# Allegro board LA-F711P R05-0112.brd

Outline 371.4 x 140.3 mm; copper layers: TOP, GND1, IN1, VCC, IN2, IN3, GND2, BOTTOM. Coordinates in mm from the lower left corner of the outline.

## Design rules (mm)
net group 5: nets PCIE_PTX_C_DRX_N5 PCIE_PTX_C_DRX_P5
net group 6: nets PCIE_PTX_C_DRX_N6 PCIE_PTX_C_DRX_P6
net group 7: nets PCIE_PTX_C_DRX_N7 PCIE_PTX_C_DRX_P7
net group DDR_ALE_S12/25: nets DDR_A_ALERT# DDR_B_ALERT#
net group DIFFPAIR12: nets CPU_DP2_AUXN CPU_DP2_AUXP
net group DIFFPAIR14: nets CPU_DP2_N0 CPU_DP2_P0
net group DIFFPAIR15: nets CPU_DP2_N0_C CPU_DP2_P0_C
net group DIFFPAIR16: nets CPU_DP2_N1 CPU_DP2_P1
net group DIFFPAIR17: nets CPU_DP2_N1_C CPU_DP2_P1_C
net group DIFFPAIR18: nets CPU_DP2_N2 CPU_DP2_P2
net group DIFFPAIR19: nets CPU_DP2_N2_C CPU_DP2_P2_C
net group DIFFPAIR20: nets CPU_DP2_N3 CPU_DP2_P3
net group DIFFPAIR21: nets CPU_DP2_N3_C CPU_DP2_P3_C
net group DIFFPAIR22: nets CPU_DP3_AUXN CPU_DP3_AUXP
net group DIFFPAIR23: nets CPU_DP3_AUXN_C CPU_DP3_AUXP_C
net group DIFFPAIR24: nets CPU_DP3_N0 CPU_DP3_P0
net group DIFFPAIR25: nets CPU_DP3_N0_C CPU_DP3_P0_C
net group DIFFPAIR26: nets CPU_DP3_N1 CPU_DP3_P1
net group DIFFPAIR27: nets CPU_DP3_N1_C CPU_DP3_P1_C
net group DIFFPAIR28: nets CPU_DP3_N2 CPU_DP3_P2
net group DIFFPAIR30: nets CPU_DP3_N3 CPU_DP3_P3
net group DIFFPAIR344: nets CLK_TP_SIO_R DAT_TP_SIO_R
net group DIFFPAIR345: nets I2C1_SCK_TP_R I2C1_SDA_TP_R
net group DIFFPAIR346: nets I2C1_SCK_TP I2C1_SDA_TP
net group DIFFPAIR347: nets CLK_TP_SIO_I2C_DAT DAT_TP_SIO_I2C_CLK
net group DIFFPAIR349: nets DMI_CRX_PTX_N0 DMI_CRX_PTX_P0
net group DIFFPAIR350: nets DMI_CRX_PTX_N1 DMI_CRX_PTX_P1
net group DIFFPAIR351: nets DMI_CRX_PTX_N2 DMI_CRX_PTX_P2
net group DIFFPAIR352: nets DMI_CRX_PTX_N3 DMI_CRX_PTX_P3
net group DIFFPAIR353: nets DMI_CTX_PRX_N0 DMI_CTX_PRX_P0
net group DIFFPAIR354: nets DMI_CTX_PRX_N1 DMI_CTX_PRX_P1
net group DIFFPAIR355: nets DMI_CTX_PRX_N2 DMI_CTX_PRX_P2
net group DIFFPAIR356: nets DMI_CTX_PRX_N3 DMI_CTX_PRX_P3
net group DIFFPAIR357: nets HDMI_CTRL_CLK HDMI_CTRL_DATA
net group DIFFPAIR359: nets PCH_CL_CLK1 PCH_CL_DATA1
net group DIFFPAIR360: nets PCH_DP1_CTRL_CLK PCH_DP1_CTRL_DATA
net group DIFFPAIR361: nets PCH_DP3_CTRL_CLK PCH_DP3_CTRL_DATA
net group DIFFPAIR365: nets TBTA_DEBUG1 TBTA_DEBUG2
net group DIFFPAIR375: nets BC_CLK_ECE1117 BC_DAT_ECE1117
net group DIFFPAIR376: nets VCC_SA_SENSE VSS_SA_SENSE
net group DIFFPAIR377: nets VCC_SENSE VSS_SENSE
net group DIFFPAIR378: nets VCC_GT_SENSE VSS_GT_SENSE
net group DIFFPAIR380: nets VCC_IO_SENSE VSS_IO_SENSE
net group DIFFPAIR382: nets PCIE_PRX_C_DTX_N6 PCIE_PRX_C_DTX_P6
net group DIFFPAIR383: nets PCIE_PRX_DTX_N6 PCIE_PRX_DTX_P6
net group DIFFPAIR384: nets PCIE_PTX_DRX_N6 PCIE_PTX_DRX_P6
net group DIFFPAIR385: nets SD_1_N1 SD_1_P1
net group DIFFPAIR386: nets SD_1_DAT0 SD_1_DAT1
net group DIFFPAIR387: nets SD_1_DAT0_R SD_1_DAT1_R
net group DIFFPAIR388: nets SD_1_N0 SD_1_P0
net group DIFFPAIR389: nets SW_USB20_1_N4 SW_USB20_1_P4
net group DIFFPAIR390: nets SW_USB20_2_N4 SW_USB20_2_P4
net group DIFFPAIR391: nets SW_USB20_1_N4_R SW_USB20_1_P4_R
net group DIFFPAIR392: nets DP2_MIC_SBU1 DP2_MIC_SBU2
net group DIFFPAIR393: nets CNV_PRX_DTX_N1 CNV_PRX_DTX_P1
net group DIFFPAIR394: nets CNV_PRX_DTX_N0 CNV_PRX_DTX_P0
net group DIFFPAIR395: nets CLK_CNV_PRX_DTX_N CLK_CNV_PRX_DTX_P
net group DIFFPAIR396: nets CLK_CNV_PTX_DRX_N CLK_CNV_PTX_DRX_P
net group DIFFPAIR397: nets CNV_PTX_DRX_N1 CNV_PTX_DRX_P1
net group DIFFPAIR398: nets CNV_PTX_DRX_N0 CNV_PTX_DRX_P0
net group DIFFPAIR399: nets PCIE_PRX_C_DTX_N5 PCIE_PRX_C_DTX_P5
net group DIFFPAIR400: nets PCIE_PRX_DTX_N5 PCIE_PRX_DTX_P5
net group DIFFPAIR401: nets PCIE_PTX_DRX_N5 PCIE_PTX_DRX_P5
net group DIFFPAIR403: nets PCIE_PTX_L_DRX_N18 PCIE_PTX_L_DRX_P18
net group DIFFPAIR404: nets PCIE_PTX_SW_DRX_N18 PCIE_PTX_SW_DRX_P18
net group DIFFPAIR405: nets PCIE_PRX_SW_DTX_N18 PCIE_PRX_SW_DTX_P18
net group DIFFPAIR406: nets PCIE_PRX_DTX_N7 PCIE_PRX_DTX_P7
net group DIFFPAIR407: nets PCIE_PTX_DRX_N7 PCIE_PTX_DRX_P7
net group DIFFPAIR408: nets CPU_DP3_N1_RD CPU_DP3_P1_RD
net group DIFFPAIR409: nets CPU_DP3_N2_C_RD CPU_DP3_P2_C_RD
net group DIFFPAIR410: nets PS8802_SBU1_R PS8802_SBU2_R
net group DP1: nets CPU_DP3_AUXN_C_RD CPU_DP3_AUXP_C_RD
net group DP2: nets CPU_DP3_AUXN_RD CPU_DP3_AUXP_RD
net group DP3: nets CPU_DP3_N0_C_RD CPU_DP3_P0_C_RD
net group DP4: nets CPU_DP3_N0_RD CPU_DP3_P0_RD
net group DP5: nets CPU_DP3_N1_C_RD CPU_DP3_P1_C_RD
net group DP7: nets CPU_DP3_N3_C_RD CPU_DP3_P3_C_RD
net group DP18: nets USB20_N8_R USB20_P8_R
net group DP19: nets USB20_N14 USB20_P14
net group DP20: nets USB20_N14_R USB20_P14_R
net group DP21: nets CHR_USB20_N1 CHR_USB20_P1
net group DP22: nets CHR_USB20_N1_R CHR_USB20_P1_R
net group PCIE_PRX_DTX_P18: nets PCIE_PRX_DTX_N18 PCIE_PRX_DTX_P18
net group PCIE_PTX_DRX_P18: nets PCIE_PTX_DRX_N18 PCIE_PTX_DRX_P18
net group SW_USB20_2_N4_R: nets SW_USB20_2_N4_R SW_USB20_2_P4_R
net group TBT_S20/20: nets TBTA_DEBUG3 TBTA_DEBUG4
net group USB3.1: nets TBTA_LSRX_R TBTA_LSTX_R
net group USB3_DP2_1_MRX_C_DTX_P5: nets USB3_DP2_1_MRX_C_DTX_N5 USB3_DP2_1_MRX_C_DTX_P5
net group USB3_DP2_2_MRX_C_DTX_N5: nets USB3_DP2_2_MRX_C_DTX_N5 USB3_DP2_2_MRX_C_DTX_P5
net group W5: nets EDP_COMP PEG_COMP
net group W15: nets PCIECOMP PCIECOMP#
net group 50H-CLK-1234: nets AUD_AZACPU_SCLK AUD_AZACPU_SCLK_R CPU_XDP_TCLK DMIC_CLK0 DMIC_CLK_CODEC ESPI_CLK HDA_BIT_CLK HDA_BIT_CLK_R SUSCLK
net group 50H_CLK: nets PCH_SPI_CLK PCH_SPI_CLK_0_R PCH_SPI_CLK_1_R PCH_SPI_CLK_2_R PCH_SPI_CLK_R1
net group 50H_SPI: nets CPU_XDP_PRS PCH_SPI_CS#0 PCH_SPI_CS#0_R1 PCH_SPI_CS#0_R2 PCH_SPI_CS#1 PCH_SPI_CS#1_R1 PCH_SPI_CS#2 PCH_SPI_CS#2_R PCH_SPI_D0 PCH_SPI_D0_0_R PCH_SPI_D0_1_R PCH_SPI_D0_2_R PCH_SPI_D0_R1 PCH_SPI_D1 PCH_SPI_D1_0_R PCH_SPI_D1_1_R PCH_SPI_D1_2_R PCH_SPI_D1_R1 PCH_SPI_D2 PCH_SPI_D2_0_R PCH_SPI_D2_1_R PCH_SPI_D2_R1 PCH_SPI_D2_XDP PCH_SPI_D3 PCH_SPI_D3_0_R PCH_SPI_D3_1_R PCH_SPI_D3_R1
net group 100H_LANTF_4.5/5.5/5.5/5.5/4.5: nets RJ45_MDIN0 RJ45_MDIN1 RJ45_MDIN2 RJ45_MDIN3 RJ45_MDIP0 RJ45_MDIP1 RJ45_MDIP2 RJ45_MDIP3
net group CARD READER: nets SD_1_CLK SD_1_CLK_R SD_1_CMD SD_1_CMD_R SD_1_DAT2 SD_1_DAT2_R SD_1_DAT3 SD_1_DAT3_R
net group CLK: nets CLKREQ_PCIE#0 CLKREQ_PCIE#1 CLKREQ_PCIE#3 CLKREQ_PCIE#4 CLKREQ_PCIE#5 CLKREQ_PCIE#6_R CLKREQ_PCIE#7_R ESPI_CLK_5105 PCI_CLK_LPC1 XCLK_RBIAS XTAL24_IN_R XTAL24_OUT_R XTAL24_OUT_R1
net group CLK_S15/20: nets CLKREQ_PCIE#0_R CLKREQ_PCIE#1_R CLKREQ_PCIE#3_R CLKREQ_PCIE#4_R CLKREQ_PCIE#5_R PCH_JTAGX SUSCLK_R TBTA_ROM_CLK_PD TBTA_ROM_CLK_PD_R WIGIG_32KHZ
net group DDR_A_S12/25: nets DDR_A_ACT# DDR_A_BA0 DDR_A_BA1 DDR_A_BG0 DDR_A_BG1 DDR_A_MA0 DDR_A_MA1 DDR_A_MA2 DDR_A_MA3 DDR_A_MA4 DDR_A_MA5 DDR_A_MA6 DDR_A_MA7 DDR_A_MA8 DDR_A_MA9 DDR_A_MA10 DDR_A_MA11 DDR_A_MA12 DDR_A_MA13 DDR_A_MA14 DDR_A_MA15 DDR_A_MA16 DDR_A_PAR DDR_B_ACT# DDR_B_BA0 DDR_B_BA1 DDR_B_BG0 DDR_B_BG1 DDR_B_MA0 DDR_B_MA1 DDR_B_MA2 DDR_B_MA3 DDR_B_MA4 DDR_B_MA5 DDR_B_MA6 DDR_B_MA7 DDR_B_MA8 DDR_B_MA9 DDR_B_MA10 DDR_B_MA11 DDR_B_MA12 DDR_B_MA13 DDR_B_MA14 DDR_B_MA15 DDR_B_MA16 DDR_B_PAR
net group DDR_C_S12/25: nets DDR_A_CS#0 DDR_A_CS#1 DDR_A_ODT0 DDR_A_ODT1 DDR_B_CS#0 DDR_B_CS#1 DDR_B_ODT0 DDR_B_ODT1
net group DDR_CKE_S12/25: nets DDR_A_CKE0 DDR_A_CKE1 DDR_B_CKE0 DDR_B_CKE1
net group DDR_DQS_S5(16)/25: nets DDR_A_DQS0 DDR_A_DQS1 DDR_A_DQS2 DDR_A_DQS3 DDR_A_DQS4 DDR_A_DQS5 DDR_A_DQS6 DDR_A_DQS7 DDR_A_DQS#0 DDR_A_DQS#1 DDR_A_DQS#2 DDR_A_DQS#3 DDR_A_DQS#4 DDR_A_DQS#5 DDR_A_DQS#6 DDR_A_DQS#7 DDR_B_DQS0 DDR_B_DQS1 DDR_B_DQS2 DDR_B_DQS3 DDR_B_DQS4 DDR_B_DQS5 DDR_B_DQS6 DDR_B_DQS7 DDR_B_DQS#0 DDR_B_DQS#1 DDR_B_DQS#2 DDR_B_DQS#3 DDR_B_DQS#4 DDR_B_DQS#5 DDR_B_DQS#6 DDR_B_DQS#7
net group DDR_RCOMP_S20/25: nets DDR_RCOMP0 DDR_RCOMP1 DDR_RCOMP2
net group DDR_RESET_S4: nets DDR4_DRAMRST#_PCH
net group DDRA_D0_S8/5(16)/25: nets DDR_A_D0 DDR_A_D1 DDR_A_D2 DDR_A_D3 DDR_A_D4 DDR_A_D5 DDR_A_D6 DDR_A_D7
net group DDRA_D1_S8/5(16)/25: nets DDR_A_D8 DDR_A_D9 DDR_A_D10 DDR_A_D11 DDR_A_D12 DDR_A_D13 DDR_A_D14 DDR_A_D15
net group DDRA_D2_S8/5(16)/25: nets DDR_A_D16 DDR_A_D17 DDR_A_D18 DDR_A_D19 DDR_A_D20 DDR_A_D21 DDR_A_D22 DDR_A_D23
net group DDRA_D3_S8/5(16)/25: nets DDR_A_D24 DDR_A_D25 DDR_A_D26 DDR_A_D27 DDR_A_D28 DDR_A_D29 DDR_A_D30 DDR_A_D31
net group DDRA_D4_S8/5(16)/25: nets DDR_A_D32 DDR_A_D33 DDR_A_D34 DDR_A_D35 DDR_A_D36 DDR_A_D37 DDR_A_D38 DDR_A_D39
net group DDRA_D5_S8/5(16)/25: nets DDR_A_D40 DDR_A_D41 DDR_A_D42 DDR_A_D43 DDR_A_D44 DDR_A_D45 DDR_A_D46 DDR_A_D47
net group DDRA_D6_S8/5(16)/25: nets DDR_A_D48 DDR_A_D49 DDR_A_D50 DDR_A_D51 DDR_A_D52 DDR_A_D53 DDR_A_D54 DDR_A_D55
net group DDRA_D7_S8/5(16)/25: nets DDR_A_D56 DDR_A_D57 DDR_A_D58 DDR_A_D59 DDR_A_D60 DDR_A_D61 DDR_A_D62 DDR_A_D63
net group DDRB_D0_S8/5(16)/25: nets DDR_B_D0 DDR_B_D1 DDR_B_D2 DDR_B_D3 DDR_B_D4 DDR_B_D5 DDR_B_D6 DDR_B_D7
net group DDRB_D1_S8/5(16)/25: nets DDR_B_D8 DDR_B_D9 DDR_B_D10 DDR_B_D11 DDR_B_D12 DDR_B_D13 DDR_B_D14 DDR_B_D15
net group DDRB_D2_S8/5(16)/25: nets DDR_B_D16 DDR_B_D17 DDR_B_D18 DDR_B_D19 DDR_B_D20 DDR_B_D21 DDR_B_D22 DDR_B_D23
net group DDRB_D3_S8/5(16)/25: nets DDR_B_D24 DDR_B_D25 DDR_B_D26 DDR_B_D27 DDR_B_D28 DDR_B_D29 DDR_B_D30 DDR_B_D31
net group DDRB_D4_S8/5(16)/25: nets DDR_B_D32 DDR_B_D33 DDR_B_D34 DDR_B_D35 DDR_B_D36 DDR_B_D37 DDR_B_D38 DDR_B_D39
net group DDRB_D5_S8/5(16)/25: nets DDR_B_D40 DDR_B_D41 DDR_B_D42 DDR_B_D43 DDR_B_D44 DDR_B_D45 DDR_B_D46 DDR_B_D47
net group DDRB_D6_S8/5(16)/25: nets DDR_B_D48 DDR_B_D49 DDR_B_D50 DDR_B_D51 DDR_B_D52 DDR_B_D53 DDR_B_D54 DDR_B_D55
net group DDRB_D7_S8/5(16)/25: nets DDR_B_D56 DDR_B_D57 DDR_B_D58 DDR_B_D59 DDR_B_D60 DDR_B_D61 DDR_B_D62 DDR_B_D63
net group DDRCLK_S16/25: nets DDR_A_CLK0 DDR_A_CLK1 DDR_A_CLK#0 DDR_A_CLK#1 DDR_B_CLK0 DDR_B_CLK1 DDR_B_CLK#0 DDR_B_CLK#1
net group DIFFPAIR13: nets CPU_DP2_AUXN_C
net group DIFFPAIR326: nets PBAT_CHARGER_SMBDAT
net group DIFFPAIR327: nets PBAT_SMBDAT_C
net group DIFFPAIR329: nets DDR_XDP_WAN_SMBDAT
net group DIFFPAIR332: nets MEM_SMBDATA
net group DIFFPAIR333: nets SML0_SMBDATA
net group DIFFPAIR334: nets SML1_SMBDATA
net group DIFFPAIR335: nets UPD1_SMBDAT
net group DIFFPAIR336: nets UPD1_SMBDAT_Q
net group DIFFPAIR337: nets UPD2_SMBDAT
net group DP: nets CPU_DP1_N0 CPU_DP1_N1 CPU_DP1_N2 CPU_DP1_N3 CPU_DP1_P0 CPU_DP1_P1 CPU_DP1_P2 CPU_DP1_P3 CPU_DP2_AUXN_C_MUX CPU_DP2_AUXP_C CPU_DP2_AUXP_C_MUX
net group EDP_S12/15: nets EDP_AUXN EDP_AUXN_C EDP_AUXP EDP_AUXP_C EDP_TXN0 EDP_TXN0_C EDP_TXN1 EDP_TXN1_C EDP_TXP0 EDP_TXP0_C EDP_TXP1 EDP_TXP1_C
net group HDMI_S12/15: nets HDMI_CLKN HDMI_CLKP HDMI_L_CLKN HDMI_L_CLKP HDMI_L_TX_N0 HDMI_L_TX_N1 HDMI_L_TX_N2 HDMI_L_TX_P0 HDMI_L_TX_P1 HDMI_L_TX_P2 HDMI_TX_N0 HDMI_TX_N1 HDMI_TX_N2 HDMI_TX_P0 HDMI_TX_P1 HDMI_TX_P2
net group LAN_S20/20: nets LAN_MDIN0 LAN_MDIN0_L LAN_MDIN1 LAN_MDIN1_L LAN_MDIN2 LAN_MDIN2_L LAN_MDIN3 LAN_MDIN3_L LAN_MDIP0 LAN_MDIP0_L LAN_MDIP1 LAN_MDIP1_L LAN_MDIP2 LAN_MDIP2_L LAN_MDIP3 LAN_MDIP3_L
net group PCIE: nets PCIE_PRX_L_DTX_N18 PCIE_PRX_L_DTX_P18 PCIE_PTX_C_DRX_N18 PCIE_PTX_C_DRX_P18 PCIE_PTX_C_SW_DRX_N18 PCIE_PTX_C_SW_DRX_P18
net group PCIE_S12/12: nets PCIE_PRX_DTX_N9 PCIE_PRX_DTX_N10 PCIE_PRX_DTX_N11 PCIE_PRX_DTX_N12 PCIE_PRX_DTX_N17 PCIE_PRX_DTX_P9 PCIE_PRX_DTX_P10 PCIE_PRX_DTX_P11 PCIE_PRX_DTX_P12 PCIE_PRX_DTX_P17 PCIE_PTX_C_DRX_N9 PCIE_PTX_C_DRX_N10 PCIE_PTX_C_DRX_N11 PCIE_PTX_C_DRX_N12 PCIE_PTX_C_DRX_N17 PCIE_PTX_C_DRX_P9 PCIE_PTX_C_DRX_P10 PCIE_PTX_C_DRX_P11 PCIE_PTX_C_DRX_P12 PCIE_PTX_C_DRX_P17 PCIE_PTX_DRX_N9 PCIE_PTX_DRX_N10 PCIE_PTX_DRX_N11 PCIE_PTX_DRX_N12 PCIE_PTX_DRX_N17 PCIE_PTX_DRX_P9 PCIE_PTX_DRX_P10 PCIE_PTX_DRX_P11 PCIE_PTX_DRX_P12 PCIE_PTX_DRX_P17
net group PLATFORM CLK: nets CLK_PCIE_N0 CLK_PCIE_N1 CLK_PCIE_N3 CLK_PCIE_N4 CLK_PCIE_N5 CLK_PCIE_P0 CLK_PCIE_P1 CLK_PCIE_P3 CLK_PCIE_P4 CLK_PCIE_P5 CPU_24MHZ_R_D CPU_24MHZ_R_D# PCH_CPU_BCLK_D PCH_CPU_BCLK_D# PCH_CPU_BCLK_R_D PCH_CPU_BCLK_R_D# PCH_CPU_NSSC_CLK_D PCH_CPU_NSSC_CLK_D# PCH_CPU_PCIBCLK_D PCH_CPU_PCIBCLK_D# PCH_CPU_PCIBCLK_R_D PCH_CPU_PCIBCLK_R_D# PCH_XDP_CLK_DN PCH_XDP_CLK_DN_R PCH_XDP_CLK_DP PCH_XDP_CLK_DP_R
net group RTC: nets PCH_RTCX1 PCH_RTCX1_R PCH_RTCX2 SRTCRST#
net group S5/15: nets AUD_AZACPU_SDI AUD_AZACPU_SDI_R AUD_AZACPU_SDO AUD_AZACPU_SDO_R DMIC0 HDA_RST# HDA_RST#_R HDA_SDIN0 HDA_SDIN0_R HDA_SDOUT HDA_SDOUT_R HDA_SYNC HDA_SYNC_R
net group S8: nets ESPI_ALERT# ESPI_CS# ESPI_IO0 ESPI_IO0_R ESPI_IO1 ESPI_IO1_R ESPI_IO2 ESPI_IO2_R ESPI_IO3 ESPI_IO3_R ESPI_RESET#
net group S10: nets +LINE1-VREFO-L +LINE1-VREFO-R +MIC2-VREFO AUD_HP_NB_SENSE AUD_HP_OUT_L AUD_HP_OUT_L1 AUD_HP_OUT_R AUD_HP_OUT_R1 AUD_SENSE_A HP_OUT_L HP_OUT_R LINE1_L LINE1_R RING2 RING2_R SLEEVE SLEEVE_R
net group S12: nets CPU_2_PCH_TRIGGER CPU_2_PCH_TRIGGER_R H_CATERR# H_PROCHOT#_R H_PWRGD H_THERMTRIP# H_THERMTRIP#_R PCH_2_CPU_TRIGGER PCH_2_CPU_TRIGGER_R PCH_PLTRST# PCH_PLTRST#_5105 PCH_PLTRST#_AND PCH_PLTRST#_EC PCH_THERMTRIP# PLTRST_CPU# PLTRST_LAN# PLTRST_TPM# VCCST_PWRGD VCCST_PWRGD_CPU VCCST_PWRGD_EC XDP_OBS0 XDP_OBS0_R XDP_OBS1 XDP_OBS1_R
net group S15: nets DDR_XDP_WAN_SMBCLK H_VCCST_PWRGD_XDP ISH_UART0_CTS# ISH_UART0_CTS#_R ISH_UART0_RTS# ISH_UART0_RTS#_R ISH_UART0_RXD ISH_UART0_RXD_R ISH_UART0_TXD ISH_UART0_TXD_R MEM_SMBCLK PBAT_CHARGER_SMBCLK PBAT_SMBCLK_C PCH_CL_RST1# PCH_DPWROK PCH_DPWROK_EC PCH_INTRUDER_HDR# PCH_PCIE_WAKE# PCH_PWROK PCH_RSMRST#_AND PCH_RTCRST# PCIE_WAKE# PCIE_WAKE#_R SIO_PWRBTN# SIO_RCIN# SML0_SMBCLK SML1_SMBCLK SYS_PWROK SYS_PWROK_R SYS_RESET# UPD1_SMBCLK UPD1_SMBCLK_Q UPD2_SMBCLK USB2_COMP XDP_DBRESET#
net group S18: nets H_PECI PCH_PECI PECI_EC_R
net group S20: nets MEC_XTAL1 MEC_XTAL2 MEC_XTAL2_R XTAL24_IN_R1 XTAL24_OUT XTALI XTALO XTALO_R
net group S40: nets H_PM_DOWN H_PM_DOWN_R H_PM_SYNC H_PM_SYNC_R
net group SATA_S15(12)/15(12): nets SATA_PRX_C_DTX_N2 SATA_PRX_C_DTX_P2 SATA_PRX_C_RD_DTX_N2 SATA_PRX_C_RD_DTX_P2 SATA_PRX_DTX_N2 SATA_PRX_DTX_P2 SATA_PRX_RD_DTX_N2 SATA_PRX_RD_DTX_P2 SATA_PTX_C_DRX_N2 SATA_PTX_C_DRX_P2 SATA_PTX_C_RD_DRX_N2 SATA_PTX_C_RD_DRX_P2 SATA_PTX_DRX_N2 SATA_PTX_DRX_P2 SATA_PTX_RD_DRX_N2 SATA_PTX_RD_DRX_P2
net group SD: nets SD_1_CD# SDWP SDWP_Q
net group SIM: nets UIM_CLK UIM_DATA UIM_RESET
net group SPI: nets PCH_SPI_CS#0_R3
net group SVID: nets CPU_VIDALERT# VR_SVID_ALERT# VR_SVID_CLK VR_SVID_DATA
net group USB2_S12/12: nets USB20_N1 USB20_N2 USB20_N2_R USB20_N3 USB20_N3_R USB20_N4 USB20_N6 USB20_N8 USB20_N9 USB20_N9_R USB20_N10 USB20_N11 USB20_N11_R USB20_P1 USB20_P2 USB20_P2_R USB20_P3 USB20_P3_R USB20_P4 USB20_P6 USB20_P8 USB20_P9 USB20_P9_R USB20_P10 USB20_P11 USB20_P11_R
net group USB3-80H: nets USB3_PRX_C_MTX_N5 USB3_PRX_C_MTX_P5 USB3_PRX_MTX_N5 USB3_PRX_MTX_P5 USB3_PTX_C_MRX_N5 USB3_PTX_C_MRX_P5 USB3_PTX_MRX_N5 USB3_PTX_MRX_P5
net group USB3.1-100H: nets USB3_DP2_1_MRX_DTX_N5 USB3_DP2_1_MRX_DTX_P5 USB3_DP2_1_MTX_C_DRX_N5 USB3_DP2_1_MTX_C_DRX_P5 USB3_DP2_1_MTX_DRX_N5 USB3_DP2_1_MTX_DRX_P5 USB3_DP2_2_MRX_DTX_N5 USB3_DP2_2_MRX_DTX_P5 USB3_DP2_2_MTX_C_DRX_N5 USB3_DP2_2_MTX_C_DRX_P5 USB3_DP2_2_MTX_DRX_N5 USB3_DP2_2_MTX_DRX_P5
net group USB3_S12/12: nets USB3_PRX_DTX_N1 USB3_PRX_DTX_N2 USB3_PRX_DTX_N3 USB3_PRX_DTX_N4 USB3_PRX_DTX_P1 USB3_PRX_DTX_P2 USB3_PRX_DTX_P3 USB3_PRX_DTX_P4 USB3_PTX_C_DRX_N1 USB3_PTX_C_DRX_N2 USB3_PTX_C_DRX_N3 USB3_PTX_C_DRX_N4 USB3_PTX_C_DRX_P1 USB3_PTX_C_DRX_P2 USB3_PTX_C_DRX_P3 USB3_PTX_C_DRX_P4 USB3_PTX_DRX_N1 USB3_PTX_DRX_N2 USB3_PTX_DRX_N3 USB3_PTX_DRX_N4 USB3_PTX_DRX_P1 USB3_PTX_DRX_P2 USB3_PTX_DRX_P3 USB3_PTX_DRX_P4
net group VGA_C_S5/10: nets CLK_DDC2_CRT DAT_DDC2_CRT ISPSCL ISPSDA
net group VGA_S20/30: nets BLUE BLUE_CRT GREEN GREEN_CRT RED RED_CRT
net group VGA_SYNC_S12/20: nets HSYNC_CONN HSYNC_CRT VSYNC_CONN VSYNC_CRT
net group W5S5: nets REM_DIODE1_N REM_DIODE1_P REM_DIODE2_N REM_DIODE2_P REM_DIODE4_N REM_DIODE4_P
net group W10: nets BAT1_LED# BAT2_LED# BATT_WHITE# BATT_YELLOW#
net group W20: nets +DDR_VREF_A_CA +DDR_VREF_B_CA +DDR_VREF_B_DQ +DDR_VREF_CA
net group W20-POWER: nets +1.0V_AMPHYPLL +1.0V_PRIM_XDP +1.0V_VCCSTG +1.2V_LDO +1.8V_RUN_CARD +1.8VALWP +1VS_VCCIOP +3.3V_ALW2 +3.3V_ALWP +3.3V_CAM +3.3V_HDD +3.3V_LAN +3.3V_LAN_UZ2 +3.3V_MMI_AUX +3.3V_MMI_IN +3.3V_RTC_LDO +3.3V_RUN_CARD +3.3V_RUN_UZ3 +3.3V_TP +5V_ALW2 +5V_ALWP +5V_RUN_AUDIO +5V_TSP +5V_USB_CHG_PWR +BL_PWR_SRC +COINCELL +DC_IN_SS +DCIN_JACK +EDP_VDD +GND_CHASSIS +LCDVDD +PBATT +PECI_VREF +PWR_SRC_AC +RSVD_VCC3P3_1 +RTC_CELL +RTC_CELL_VBAT +SDC_IN +VCHGR +VDDA_AVDD1 +VR_CAP
net group W40: nets INT_SPK_L+ INT_SPK_L- INT_SPK_R+ INT_SPK_R- INT_SPKR_L+ INT_SPKR_L- INT_SPKR_R+ INT_SPKR_R-
nets with their own width: min track width 0.152; nets VCCMPHY_SENSE VSSMPHY_SENSE
nets with their own width: min track width 0.508; nets +3.3V_M_TPM +UZ12_TPM

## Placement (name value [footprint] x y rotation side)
CA1  680P_0402_50V7K  [C_0402]  349.17 37.92 90 bottom
CA2  330P_0402_50V8J  [C_0402]  354.38 31.19 90 top
CA3  330P_0402_50V8J  [C_0402]  350.19 31.44 90 top
CA4  680P_0402_50V7K  [C_0402]  349.07 34.9 90 bottom
CA5  27P_0402_50V8J  [C_0402]  121.7 103.42 270 bottom
CA6  82P_0402_50V8J  [C_0402]  122.97 103.42 270 bottom
CA7  0.1U_0201_10V6K  [C_0201]  120.72 103.72 180 bottom
CA8  0.1U_0201_10V6K  [C_0201]  344.56 42.57 0 top
CA9  10U_0603_10V6M  [C_0603]  345.07 43.49 90 top
CA10  0.1U_0201_10V6K  [C_0201]  338.79 33.3 180 top
CA12  680P_0402_50V7K  [C_0402]  349.86 39.71 45 bottom
CA13  680P_0402_50V7K  [C_0402]  352.8 38.07 225 bottom
CA19  1000P_0402_50V7K  [C_0402]  334.92 35.1 180 top
CA22  1000P_0402_50V7K  [C_0402]  334.92 37.77 180 top
CA23  1000P_0402_50V7K  [C_0402]  334.92 36.88 180 top
CA24  1000P_0402_50V7K  [C_0402]  334.92 35.99 180 top
CA25  10U_0603_10V6M  [C_0603]  346.72 38.15 0 top
CA27  0.1U_0402_25V6  [C_0402]  350.54 34.53 180 top
CA28  0.1U_0402_25V6  [C_0402]  347.94 35.49 180 top
CA29  1U_0603_10V6K  [C_0603]  339.71 40.82 180 bottom
CA31  1U_0603_10V6K  [C_0603]  336.19 32.47 270 top
CA33  10P_0402_50V8J  [C_0402]  341.55 29.06 270 top
CA35  2.2U_0402_6.3V6M  [C_0402]  343.99 43.79 90 top
CA41  0.1U_0402_25V6  [C_0402]  347.19 33.17 0 top
CA43  10U_0603_10V6M  [C_0603]  346.85 42.53 0 top
CA44  10U_0603_10V6M  [C_0603]  346.85 41.26 0 top
CA45  0.1U_0201_10V6K  [C_0201]  333.74 39.42 90 top
CA46  10U_0603_10V6M  [C_0603]  332.94 39.23 180 top
CA47  0.1U_0201_10V6K  [C_0201]  335.96 33.84 270 top
CA48  10U_0603_10V6M  [C_0603]  334.82 33.87 270 top
CA49  1U_0603_10V6K  [C_0603]  339.42 42.6 180 top
CA51  10U_0603_10V6M  [C_0603]  343.93 43.42 90 bottom
CA52  10U_0603_10V6M  [C_0603]  336.72 40.66 90 top
CA53  10U_0603_10V6M  [C_0603]  341.51 34.72 0 bottom
CA54  100P_0402_50V8J~D  [C_0402]  340.66 29.06 270 top
CA55  0.1U_0201_10V6K  [C_0201]  343.25 33.39 0 bottom
CA56  10U_0603_10V6M  [C_0603]  343.55 32.56 270 bottom
CA57  0.1U_0201_10V6K  [C_0201]  336.28 39.04 180 top
CA58  10U_0603_10V6M  [C_0603]  336.23 43.49 90 top
CA59  10U_0603_10V6M  [C_0603]  333.61 27.71 0 top
CA60  0.1U_0201_10V6K  [C_0201]  331.77 32.17 90 top
CA61  10U_0603_10V6M  [C_0603]  338.69 32.41 180 top
CA62  100P_0402_50V8J  [C_0402]  352.66 36.91 45 top
CA63  12P_0402_50V8J  [C_0402]  334.06 29.26 0 top
CA64  68P_0402_50V8J  [C_0402]  334.06 30.15 0 top
CA65  12P_0402_50V8J  [C_0402]  334.03 44.89 180 top
CA66  68P_0402_50V8J  [C_0402]  335.58 47.65 90 top
CA67  12P_0402_50V8J  [C_0402]  338.55 27.2 0 top
CA68  68P_0402_50V8J  [C_0402]  345.23 30.71 270 top
CA69  33P_0402_50V8J  [C_0402]  338.62 45.33 90 top
CA72  100P_0402_50V8J  [C_0402]  353.29 36.28 45 top
CA73  2P_0402_50V8C  [C_0402]  217.71 39.8 270 bottom
CA74  2P_0402_50V8C  [C_0402]  220.07 37.5 180 bottom
CA75  2P_0402_50V8C  [C_0402]  219.17 40.94 270 bottom
CA76  2P_0402_50V8C  [C_0402]  219.5 38.58 180 bottom
CC28  0.1U_0402_25V6  [C_0402]  41.91 36.47 180 top
CC29  0.1U_0402_25V6  [C_0402]  41.05 48.1 90 top
CC32  0.1U_0402_25V6  [C_0402]  44.73 48.15 90 top
CC33  0.1U_0402_25V6  [C_0402]  53.26 44.78 90 top
CC81  22U_0603_6.3V6M  [C_0603]  114.33 44.88 45 top
CC82  22U_0603_6.3V6M  [C_0603]  103.84 48.29 0 top
CC83  22U_0603_6.3V6M  [C_0603]  96.48 48.07 0 top
CC84  22U_0603_6.3V6M  [C_0603]  112.56 46.66 45 top
CC161  10U_0603_6.3V6M~D  [C_0603]  93.4 59.56 180 top
CC163  10U_0603_6.3V6M~D  [C_0603]  96.99 45.03 0 top
CC164  10U_0603_6.3V6M~D  [C_0603]  101.88 61.38 90 top
CC165  10U_0603_6.3V6M~D  [C_0603]  96.48 46.68 0 top
CC166  10U_0603_6.3V6M~D  [C_0603]  101.81 45.24 180 top
CC167  10U_0603_6.3V6M~D  [C_0603]  101.74 46.68 180 top
CC168  10U_0603_6.3V6M~D  [C_0603]  91.78 47.06 0 top
CC170  10U_0603_6.3V6M~D  [C_0603]  101.81 43.97 180 top
CC171  10U_0603_6.3V6M~D  [C_0603]  113.45 45.77 45 top
CC172  10U_0603_6.3V6M~D  [C_0603]  108.65 46.9 45 top
CC185  10U_0603_6.3V6M~D  [C_0603]  108.38 60.92 0 top
CC186  1U_0201_6.3V6M  [C_0201]  128.39 71.6 180 top
CC187  10U_0603_6.3V6M  [C_0603]  127.62 68.12 90 top
CC188  10U_0603_6.3V6M  [C_0603]  115.86 64.79 180 top
CC189  10U_0603_6.3V6M  [C_0603]  115.9 66 180 top
CC191  1U_0201_6.3V6M  [C_0201]  130.17 74.19 180 top
CC192  1U_0201_6.3V6M  [C_0201]  114.69 72.41 0 top
CC193  1U_0402_6.3V6K  [C_0402]  131.8 74.19 0 top
CC194  1U_0402_6.3V6K  [C_0402]  131.8 75.21 0 top
CC195  1U_0201_6.3V6M  [C_0201]  130.55 73.05 180 top
CC209  1U_0201_6.3V6M  [C_0201]  73.03 63.21 270 top
CC210  1U_0201_6.3V6M  [C_0201]  73.92 63.21 270 top
CC269  0.1U_0402_25V6  [C_0402]  52.75 47.95 90 top
CC272  10U_0603_6.3V6M  [C_0603]  115.87 67.21 180 top
CC300  100P_0402_50V8J  [C_0402]  74.99 74.74 270 bottom
CC301  100P_0402_50V8J  [C_0402]  139.24 59.04 0 top
CC302  0.1U_0402_25V6  [C_0402]  212.26 46.9 180 bottom
CC303  0.1U_0402_25V6  [C_0402]  206.02 51.16 90 bottom
CC304  0.1U_0402_25V6  [C_0402]  204.96 51.16 90 bottom
CC305  0.1U_0402_25V6  [C_0402]  205.88 46.97 270 bottom
CC306  0.1U_0402_25V6  [C_0402]  45.62 48.1 90 top
CC307  0.1U_0402_25V6  [C_0402]  39.92 36.42 270 top
CC308  0.1U_0402_25V6  [C_0402]  72.86 71.3 270 top
CC310  0.1U_0201_10V6K  [C_0201]  221.26 38.32 270 top
CC311  0.1U_0201_10V6K  [C_0201]  188.67 46.03 90 bottom
CC316  33P_0402_50V8J  [C_0402]  221.78 21.55 0 top
CC318  33P_0402_50V8J  [C_0402]  220.77 31.81 180 bottom
CC319  33P_0402_50V8J  [C_0402]  226.63 30.98 0 top
CC320  33P_0402_50V8J  [C_0402]  226.31 29.36 0 bottom
CC322  2.2P_0402_50V8C  [C_0402]  74.79 62.3 90 top
CC323  0.1U_0402_25V6  [C_0402]  121.06 85.94 270 top
CC324  0.1U_0402_25V6  [C_0402]  72.72 73.96 180 bottom
CC325  33P_0402_50V8J  [C_0402]  77.05 84.8 0 top
CC327  2.2P_0402_50V8C  [C_0402]  220.52 39.26 270 top
CC328  2.2P_0402_50V8C  [C_0402]  201.58 28.36 0 top
CC329  0.1U_0201_10V6K  [C_0201]  222.85 39.06 270 top
CC330  0.1U_0201_10V6K  [C_0201]  186.13 47.52 0 bottom
CC331  0.1U_0201_10V6K  [C_0201]  191.97 46.98 90 bottom
CC332  0.1U_0201_10V6K  [C_0201]  190.19 47.57 270 bottom
CC333  22U_0603_6.3V6M  [C_0603]  129.27 67.65 90 top
CC334  0.1U_0402_25V6  [C_0402]  59.74 57.19 270 bottom
CC335  0.1U_0402_25V6  [C_0402]  130.6 59.03 270 bottom
CD1  10U_0603_6.3V6M  [C_0603]  36.22 22.82 270 top
CD2  10U_0603_6.3V6M  [C_0603]  88.95 23.39 270 top
CD3  10U_0603_6.3V6M  [C_0603]  30.34 14.25 0 top
CD4  10U_0603_6.3V6M  [C_0603]  84.99 13.17 90 top
CD5  10U_0603_6.3V6M  [C_0603]  58.7 22.82 270 top
CD6  10U_0603_6.3V6M  [C_0603]  60.23 13.55 90 top
CD7  10U_0603_6.3V6M  [C_0603]  70.39 22.7 270 top
CD8  10U_0603_6.3V6M  [C_0603]  66.09 13.35 90 top
CD9  1U_0402_6.3V6K  [C_0402]  46.77 22.82 270 top
CD10  1U_0402_6.3V6K  [C_0402]  55.66 22.82 270 top
CD11  1U_0402_6.3V6K  [C_0402]  41.43 13.65 90 top
CD12  1U_0402_6.3V6K  [C_0402]  63.53 13.65 90 top
CD13  1U_0402_6.3V6K  [C_0402]  66.7 22.82 270 top
CD14  1U_0402_6.3V6K  [C_0402]  55.91 13.65 90 top
CD15  1U_0402_6.3V6K  [C_0402]  74.45 13.65 90 top
CD16  1U_0402_6.3V6K  [C_0402]  78.66 22.71 270 top
CD17  330U_D3_2.5VY_R6M  [C_D3]  38.43 27.46 180 top
CD18  1U_0402_6.3V6K  [C_0402]  95.86 21.36 0 top
CD19  1U_0402_6.3V6K  [C_0402]  95.86 22.25 0 top
CD20  10U_0603_6.3V6M  [C_0603]  90.34 25.62 90 top
CD21  10U_0603_6.3V6M  [C_0603]  91.61 25.62 90 top
CD22  10U_0603_6.3V6M  [C_0603]  91.98 14.44 180 top
CD23  1U_0402_6.3V6K  [C_0402]  93.88 14.57 270 top
CD24  1U_0402_6.3V6K  [C_0402]  94.77 14.57 270 top
CD25  0.1U_0402_10V6K  [C_0402]  71.02 13.65 90 top
CD26  2.2U_0402_6.3V6M  [C_0402]  70.13 13.65 90 top
CD27  2.2U_0402_6.3V6M  [C_0402]  93.65 19.91 270 top
CD28  0.1U_0201_10V6K  [C_0201]  94.41 19.62 270 top
CD29  0.1U_0402_10V6K  [C_0402]  54.89 13.65 90 top
CD31  0.022U_0402_16V7K  [C_0402]  68.23 14.57 270 top
CD32  0.1U_0402_25V6  [C_0402]  66.9 61.34 0 bottom
CD33  10U_0603_6.3V6M  [C_0603]  116.63 22.5 270 top
CD34  10U_0603_6.3V6M  [C_0603]  171.23 22.95 270 top
CD35  10U_0603_6.3V6M  [C_0603]  111.92 13.17 90 top
CD36  10U_0603_6.3V6M  [C_0603]  166.95 15.33 90 top
CD37  10U_0603_6.3V6M  [C_0603]  141.78 22.5 270 top
CD38  10U_0603_6.3V6M  [C_0603]  134.67 22.5 270 top
CD39  10U_0603_6.3V6M  [C_0603]  137.04 14.27 0 top
CD40  10U_0603_6.3V6M  [C_0603]  132.76 13.49 90 top
CD41  1U_0402_6.3V6K  [C_0402]  127.79 22.82 270 top
CD42  1U_0402_6.3V6K  [C_0402]  160.05 22.85 270 top
CD43  1U_0402_6.3V6K  [C_0402]  122.46 13.65 90 top
CD44  1U_0402_6.3V6K  [C_0402]  156.19 14.42 270 top
CD45  1U_0402_6.3V6K  [C_0402]  151.56 22.63 270 top
CD46  1U_0402_6.3V6K  [C_0402]  144.7 13.61 90 top
CD47  1U_0402_6.3V6K  [C_0402]  147.37 22.63 270 top
CD48  1U_0402_6.3V6K  [C_0402]  141.13 13.65 90 top
CD49  330U_D3_2.5VY_R6M  [C_D3]  167.81 28.6 270 top
CD50  1U_0402_6.3V6K  [C_0402]  175.42 20.28 270 top
CD51  1U_0402_6.3V6K  [C_0402]  176.31 20.28 270 top
CD52  10U_0603_6.3V6M  [C_0603]  177.45 20.79 270 top
CD53  10U_0603_6.3V6M  [C_0603]  178.74 20.34 90 top
CD54  10U_0603_6.3V6M  [C_0603]  177.21 13.74 90 top
CD55  1U_0402_6.3V6K  [C_0402]  175.69 13.87 180 top
CD56  1U_0402_6.3V6K  [C_0402]  175.69 14.76 180 top
CD57  0.1U_0402_10V6K  [C_0402]  152.05 14.57 270 top
CD58  2.2U_0402_6.3V6M  [C_0402]  151.16 14.57 270 top
CD59  2.2U_0402_6.3V6M  [C_0402]  174.4 24.98 180 top
CD60  0.1U_0201_10V6K  [C_0201]  174.27 24.22 180 top
CD61  0.1U_0402_10V6K  [C_0402]  135.94 13.92 90 top
CD62  0.022U_0402_16V7K  [C_0402]  147.37 13.54 90 top
CD63  330U_2V_M  [C_5X4P5]  140.38 52.22 180 bottom
CD64  330U_2V_M  [C_5X4P5]  61.9 50.44 270 bottom
CE3  2200P_0402_50V7K  [C_0402]  313.43 35.33 180 bottom
CE4  2200P_0402_50V7K  [C_0402]  313.31 33.43 180 bottom
CE8  .047U_0402_16V7K  [C_0402]  320.26 27.96 0 top
CE10  1U_0402_6.3V6K  [C_0402]  312.28 49.45 270 top
CE11  0.1U_0201_10V6K  [C_0201]  314.28 41.55 180 bottom
CE12  2.2U_0402_6.3V6M  [C_0402]  314.61 46.95 180 top
CE13  0.1U_0201_10V6K  [C_0201]  311.45 35.37 270 top
CE14  1U_0402_6.3V6K  [C_0402]  318.27 43.78 0 top
CE15  0.1U_0201_10V6K  [C_0201]  313.36 32.66 180 bottom
CE16  10U_0603_6.3V6M  [C_0603]  306.88 38.82 90 top
CE17  22U_0603_6.3V6M  [C_0603]  310.54 38.54 270 top
CE18  0.1U_0201_10V6K  [C_0201]  311.43 37.68 270 top
CE19  0.1U_0201_10V6K  [C_0201]  318.73 36.09 180 bottom
CE20  0.1U_0201_10V6K  [C_0201]  319.96 30.29 270 bottom
CE21  0.1U_0201_10V6K  [C_0201]  316.4 28.13 270 top
CE22  0.1U_0201_10V6K  [C_0201]  310.94 10.48 270 top
CE23  0.1U_0201_10V6K  [C_0201]  318.27 42.82 0 top
CE24  2200P_0402_50V7K  [C_0402]  320.7 42.89 180 top
CE25  0.1U_0201_10V6K  [C_0201]  322.84 33.93 0 bottom
CE26  2200P_0402_50V7K  [C_0402]  322.2 44.22 180 top
CE27  2200P_0402_50V7K  [C_0402]  323.24 42.89 180 top
CE28  12P_0402_50V8J  [C_0402]  312.8 42.7 180 top
CE29  12P_0402_50V8J  [C_0402]  313.66 43.59 0 top
CE30  1U_0402_6.3V6K  [C_0402]  325.8 39.73 270 top
CE31  1U_0402_6.3V6K  [C_0402]  310.56 33.15 270 top
CE32  10U_0603_6.3V6M  [C_0603]  205.67 67.41 270 top
CE35  100P_0402_50V8J  [C_0402]  94.56 64.01 180 top
CE36  0.1U_0402_25V6  [C_0402]  323.21 12.6 180 top
CE37  100P_0402_50V8J  [C_0402]  14.52 104.98 270 bottom
CE38  0.1U_0402_25V6  [C_0402]  320.98 40.08 90 bottom
CE39  100P_0402_50V8J  [C_0402]  100.81 105.4 180 bottom
CE40  4700P_0402_25V7K  [C_0402]  325.73 35.71 0 top
CE46  100P_0402_50V8J  [C_0402]  81.36 10.45 90 bottom
CE47  4700P_0402_25V7K  [C_0402]  322.99 32.73 0 bottom
CE52  0.1U_0402_25V6K  [C_0402]  338.61 51.4 180 top
CE53  0.1U_0402_25V6K  [C_0402]  342.93 51.65 180 top
CE54  10P_0402_50V8J  [C_0402]  313.94 37.24 180 bottom
CE57  33P_0402_50V8J  [C_0402]  316.48 35.2 180 bottom
CE59  12P_0402_50V8J  [C_0402]  308.15 25.17 270 top
CE60  68P_0402_50V8J  [C_0402]  304.87 37.54 180 top
CE61  68P_0402_50V8J  [C_0402]  308.53 49.94 135 top
CE62  4700P_0402_25V7K  [C_0402]  309.6 40.28 0 top
CE63  1U_0402_6.3V6K  [C_0402]  308.52 55.48 180 top
CE64  0.1U_0402_25V6  [C_0402]  313.35 55.38 270 top
CE65  22P_0402_50V8J  [C_0402]  316.94 53.82 90 top
CE66  0.1U_0402_25V6  [C_0402]  328.71 46.02 90 top
CH4  15P_0402_50V8J  [C_0402]  215.92 12.2 90 bottom
CH5  15P_0402_50V8J  [C_0402]  219.62 14.82 180 bottom
CH9  0.1U_0201_10V6K  [C_0201]  225.65 20.01 180 bottom
CH10  0.1U_0402_25V6  [C_0402]  215.48 51.48 270 bottom
CH13  15P_0402_50V8J  [C_0402]  200.62 47.47 315 bottom
CH14  15P_0402_50V8J  [C_0402]  198.05 46.94 180 bottom
CH20  1U_0402_6.3VAK  [C_0402]  189.43 47.73 270 bottom
CH21  1U_0402_6.3VAK  [C_0402]  214.66 37.89 270 top
CH22  4.7U_0402_6.3V6M  [C_0402]  215.55 37.89 270 top
CH29  1U_0402_6.3VAK  [C_0402]  200.61 42.65 270 top
CH30  4.7U_0402_6.3V6M  [C_0402]  218.61 44.54 0 bottom
CH31  1U_0402_6.3VAK  [C_0402]  187.91 45.87 90 bottom
CH32  1U_0402_6.3VAK  [C_0402]  196.41 43.04 270 top
CH33  1U_0402_6.3VAK  [C_0402]  217.77 17.32 270 top
CH34  1U_0402_6.3VAK  [C_0402]  199.73 32.47 90 top
CH35  1U_0402_6.3VAK  [C_0402]  219.28 20.8 0 bottom
CH36  1U_0402_6.3VAK  [C_0402]  205.57 36.21 90 top
CH37  1U_0402_6.3VAK  [C_0402]  219.61 43.14 90 top
CH38  0.1U_0402_25V6  [C_0402]  200.62 32.47 90 top
CH40  1U_0402_6.3VAK  [C_0402]  212.78 12.24 90 bottom
CH41  1U_0402_6.3VAK  [C_0402]  214.63 18.24 180 top
CH44  0.1U_0201_10V6K  [C_0201]  200.56 34.68 270 top
CH45  22U_0805_6.3V6M~D  [C_0805]  196.88 44.93 90 top
CH46  1U_0402_6.3VAK  [C_0402]  197.3 43.04 270 top
CH47  22U_0603_6.3V6M  [C_0603]  198.66 32.23 90 top
CH62  0.1U_0201_10V6K  [C_0201]  205.83 27.11 90 top
CH63  0.1U_0402_25V6  [C_0402]  219.93 18.43 90 bottom
CH64  0.1U_0201_10V6K  [C_0201]  202.4 26.98 90 top
CH65  0.1U_0402_25V6  [C_0402]  218.66 17.32 270 top
CH66  0.1U_0402_25V6  [C_0402]  199.24 21.29 0 top
CH67  0.1U_0402_25V6  [C_0402]  217.78 42.93 135 top
CH68  0.1U_0201_10V6K  [C_0201]  219.1 19.76 270 bottom
CH266  0.01U_0402_25V7K~D  [C_0402]  216.89 20.29 180 top
CH267  1U_0402_6.3VAK  [C_0402]  192.99 16.24 270 bottom
CH268  47P_0402_50V8J  [C_0402]  223.13 41.8 180 bottom
CH270  0.1U_0201_10V6K  [C_0201]  237.03 6.16 270 bottom
CH321  33P_0402_50V8J  [C_0402]  239.01 4.72 180 bottom
CH322  33P_0402_50V8J  [C_0402]  224.61 19.07 0 bottom
CH323  4.7U_0402_6.3V6M  [C_0402]  220.56 43.14 90 top
CH324  22U_0805_6.3V6M~D  [C_0805]  194.38 16.63 270 bottom
CH340  0.1U_0402_25V6K  [C_0402]  204.73 7.09 0 bottom
CH341  0.033U_0402_16V7  [C_0402]  186.86 45.86 90 top
CH342  0.033U_0402_16V7  [C_0402]  173.33 49.49 0 bottom
CH343  0.033U_0402_16V7  [C_0402]  221.41 23.25 90 top
CH344  0.033U_0402_16V7  [C_0402]  218.49 24.78 90 top
CH345  0.033U_0402_16V7  [C_0402]  182.29 32.21 90 bottom
CH346  0.033U_0402_16V7  [C_0402]  222.74 23.82 90 bottom
CH347  0.033U_0402_16V7  [C_0402]  220.52 23.25 90 top
CH348  0.033U_0402_16V7  [C_0402]  224.53 25.04 180 bottom
CI1  100U_1206_6.3V6M  [C_1206]  18.59 95.85 90 bottom
CI3  0.1U_0201_10V6K  [C_0201]  18.55 92.86 0 bottom
CI4  0.1U_0402_25V6  [C_0402]  22.13 92.8 0 top
CI5  0.1U_0402_25V6  [C_0402]  22.13 91.91 0 top
CI6  10U_0603_10V6M  [C_0603]  22.84 93.75 180 bottom
CI7  0.1U_0201_10V6K  [C_0201]  22.31 94.89 180 bottom
CI8  100U_1206_6.3V6M  [C_1206]  92.99 122.26 180 bottom
CI9  100P_0402_50V8J  [C_0402]  100.12 122.12 90 bottom
CI10  0.1U_0201_10V6K  [C_0201]  90.07 122.52 270 top
CI11  10U_0603_10V6M  [C_0603]  101.27 121.88 90 bottom
CI12  0.1U_0201_10V6K  [C_0201]  99.34 122.14 90 bottom
CI13  0.1U_0402_25V6  [C_0402]  350.7 67.66 180 bottom
CI14  100U_1206_6.3V6M  [C_1206]  353.3 63.02 180 bottom
CI16  0.1U_0402_25V6  [C_0402]  350.68 66.77 180 bottom
CI17  0.1U_0201_10V6K  [C_0201]  354.63 65.65 90 bottom
CI19  0.1U_0201_10V6K  [C_0201]  339.5 65.88 270 top
CI27  0.1U_0402_25V6  [C_0402]  87.41 121.63 0 bottom
CI28  0.1U_0402_25V6  [C_0402]  87.41 122.52 0 bottom
CI31  10U_0402_6.3V6M  [C_0402]  338.48 65.88 270 top
CI32  150U_B2_6.3VM_R35M  [C_B2]  353.47 60.29 0 bottom
CI33  47U_0603_6.3V6M  [C_0603]  337.09 65.88 270 top
CI34  47U_0603_6.3V6M  [C_0603]  335.44 65.88 270 top
CI43  12P_0402_50V8J  [C_0402]  352.85 65.61 90 bottom
CI44  68P_0402_50V8J  [C_0402]  353.87 65.61 90 bottom
CI45  12P_0402_50V8J  [C_0402]  18.51 94.51 0 bottom
CI46  68P_0402_50V8J  [C_0402]  18.51 93.62 0 bottom
CI47  12P_0402_50V8J  [C_0402]  90.83 122.52 270 top
CI48  68P_0402_50V8J  [C_0402]  91.72 122.52 270 top
CL1  0.1U_0402_25V6  [C_0402]  318.8 80.1 90 top
CL2  0.1U_0402_25V6  [C_0402]  319.76 80.09 90 top
CL3  0.1U_0201_10V6K  [C_0201]  330.1 87.21 0 top
CL4  10U_0603_10V6M  [C_0603]  330.1 86.2 0 top
CL5  0.1U_0402_25V6  [C_0402]  321.03 80.09 90 top
CL6  0.1U_0402_25V6  [C_0402]  322.05 80.09 90 top
CL7  0.1U_0201_10V6K  [C_0201]  315.73 87.24 180 top
CL8  0.1U_0201_10V6K  [C_0201]  320.01 89.6 270 bottom
CL9  0.1U_0201_10V6K  [C_0201]  324.62 88.11 180 bottom
CL10  0.1U_0201_10V6K  [C_0201]  320.33 82.99 90 bottom
CL11  0.1U_0201_10V6K  [C_0201]  324.62 86.9 180 bottom
CL12  22U_0603_6.3V6M  [C_0603]  323.76 80.93 270 top
CL13  27P_0402_50V8J  [C_0402]  328.4 88.94 270 top
CL14  27P_0402_50V8J  [C_0402]  328.4 89.81 90 top
CL15  0.1U_0201_10V6K  [C_0201]  313.34 90.51 90 top
CL16  0.1U_0201_10V6K  [C_0201]  336.08 107.37 0 bottom
CL17  0.1U_0201_10V6K  [C_0201]  333.08 107.37 180 bottom
CL18  470P_0402_50V7K  [C_0402]  317.42 113.56 180 top
CL19  0.1U_0201_10V6K  [C_0201]  344.51 123.57 0 bottom
CL20  0.1U_0201_10V6K  [C_0201]  330.08 107.37 180 bottom
CL21  0.1U_0201_10V6K  [C_0201]  327.08 107.37 180 bottom
CL22  10P_1808_3KV8J  [C_1808]  339.96 112.79 90 bottom
CL28  22U_0805_6.3V6M  [C_0805]  326.78 84.61 0 top
CL29  12P_0402_50V8J  [C_0402]  321.16 89.51 270 bottom
CL30  82P_0402_50V8J  [C_0402]  315.83 87.97 180 top
CMOS1  SHORT PADS~D  [SHORTPADS]  227.21 37.73 270 bottom
CN1  10U_0603_10V6M  [C_0603]  275.52 3.9 270 top
CN2  0.1U_0201_10V6K  [C_0201]  274.3 3.77 270 top
CN3  0.1U_0201_10V6K  [C_0201]  272.67 6.69 90 top
CN4  0.01UF_0402_25V7K  [C_0402]  255.68 16.6 90 bottom
CN5  0.01UF_0402_25V7K  [C_0402]  256.57 16.6 90 bottom
CN6  0.01UF_0402_25V7K  [C_0402]  257.46 16.6 90 bottom
CN7  0.01UF_0402_25V7K  [C_0402]  258.35 16.6 90 bottom
CN8  1000P_0402_50V7K  [C_0402]  264.57 17.11 0 bottom
CN9  0.1U_0201_10V6K  [C_0201]  264.57 16.35 0 bottom
CN10  0.1U_0201_10V6K  [C_0201]  260.51 16.88 0 bottom
CN11  0.1U_0201_10V6K  [C_0201]  260.51 16.3 0 bottom
CN12  0.01UF_0402_25V7K  [C_0402]  243.49 15.58 0 bottom
CN13  0.01UF_0402_25V7K  [C_0402]  243.49 16.47 0 bottom
CN14  0.01UF_0402_25V7K  [C_0402]  243.49 17.36 0 bottom
CN15  0.01UF_0402_25V7K  [C_0402]  243.49 18.25 0 bottom
CN16  0.01UF_0402_25V7K  [C_0402]  250.36 20.27 90 bottom
CN17  0.1U_0201_10V6K  [C_0201]  246.93 12.72 270 bottom
CN60  68P_0402_50V8J  [C_0402]  343.06 4.54 90 top
CN61  0.1U_0201_10V6K  [C_0201]  343.95 4.54 90 top
CN62  0.1U_0201_10V6K  [C_0201]  356.28 5.96 90 top
CN63  22U_0603_6.3V6M  [C_0603]  358.8 5.42 90 top
CN64  22U_0603_6.3V6M  [C_0603]  357.41 5.42 90 top
CN65  0.22U_0402_10V6K  [C_0402]  358.17 12.33 90 bottom
CN66  0.22U_0402_10V6K  [C_0402]  357.28 12.33 90 bottom
CN67  0.22U_0402_10V6K  [C_0402]  354.87 12.33 90 bottom
CN68  0.22U_0402_10V6K  [C_0402]  353.98 12.33 90 bottom
CN69  0.22U_0402_10V6K  [C_0402]  351.82 12.33 90 bottom
CN70  0.22U_0402_10V6K  [C_0402]  350.93 12.33 90 bottom
CN71  0.22U_0402_10V6K  [C_0402]  349.41 12.33 90 bottom
CN72  0.22U_0402_10V6K  [C_0402]  348.52 12.33 90 bottom
CR1  4.7U_0402_6.3V6M  [C_0402]  17.87 72.93 0 top
CR2  0.1U_0201_10V6K  [C_0201]  18.23 72.1 0 top
CR3  0.1U_0201_10V6K  [C_0201]  16.9 63.85 180 top
CR4  10U_0402_6.3V6M  [C_0402]  16.88 63.02 180 top
CR5  4.7U_0603_6.3V6K  [C_0603]  14.9 64.04 270 top
CR6  0.1U_0201_10V6K  [C_0201]  19.41 63.82 270 top
CR7  0.1U_0201_10V6K  [C_0201]  18.77 63.82 270 top
CR11  0.1U_0402_25V6  [C_0402]  12.92 69.31 0 top
CR12  0.1U_0402_25V6  [C_0402]  12.92 68.36 0 top
CR13  0.1U_0402_25V6  [C_0402]  12.92 66.83 0 top
CR14  0.1U_0402_25V6  [C_0402]  12.92 65.88 0 top
CR15  1U_0402_6.3V6K  [C_0402]  20.75 72.29 90 top
CR17  0.1U_0201_10V6K  [C_0201]  30.39 63.3 90 top
CR18  4.7U_0603_6.3V6K  [C_0603]  29.44 62.71 90 top
CR19  0.1U_0201_10V6K  [C_0201]  5.38 81.56 270 top
CR20  4.7U_0603_6.3V6K  [C_0603]  4.36 81.56 270 top
CR21  5P_0402_50V8C  [C_0402]  23.73 65.99 90 top
CR22  1U_0402_6.3V6K  [C_0402]  21.94 66.89 0 top
CR25  12P_0402_50V8J  [C_0402]  18 62.26 0 top
CR26  82P_0402_50V8J  [C_0402]  18 61.24 0 top
CR27  12P_0402_50V8J  [C_0402]  17.87 73.88 0 top
CR28  82P_0402_50V8J  [C_0402]  17.87 74.83 0 top
CT22  100P_0402_50V8J~D  [C_0402]  36.76 81.03 180 bottom
CT44  0.1U_0402_25V6  [C_0402]  22.64 117.06 0 bottom
CT45  0.1U_0402_25V6  [C_0402]  19.88 113.16 0 top
CT46  0.01UF_0402_25V7K  [C_0402]  20.48 114.39 0 top
CT47  0.1U_0402_25V6  [C_0402]  23.72 116.74 0 top
CT48  0.01UF_0402_25V7K  [C_0402]  22.64 117.94 0 bottom
CT70  .1U_0402_16V7K  [C_0402]  50.59 94.4 270 bottom
CT71  2.2U_0402_25V6K  [C_0402]  28.22 86.96 180 bottom
CT72  2.2U_0402_25V6K  [C_0402]  27.99 82.91 270 bottom
CT73  2.2U_0402_25V6K  [C_0402]  28.06 91.85 180 top
CT74  1U_0402_10V6K  [C_0402]  28.22 85.18 270 top
CT75  22U_0805_25V6M  [C_0805]  38.48 79.25 0 bottom
CT76  22U_0805_25V6M  [C_0805]  38.48 80.97 0 bottom
CT77  22U_0805_25V6M  [C_0805]  38.5 82.73 0 bottom
CT78  22U_0805_25V6M  [C_0805]  38.53 84.48 0 bottom
CT80  0.1U_0201_10V6K  [C_0201]  27.59 91.78 0 bottom
CT81  0.1U_0201_10V6K  [C_0201]  27.59 91.15 0 bottom
CT82  1U_0603_25V6K  [C_0603]  37.75 91.91 0 bottom
CT83  1U_0402_10V6K  [C_0402]  28.22 89.5 180 bottom
CT84  10U_0603_6.3V6M  [C_0603]  28.22 88.36 180 bottom
CT85  470P_0402_50V7K  [C_0402]  37.61 95.39 90 bottom
CT86  470P_0402_50V7K  [C_0402]  36.74 95.39 90 bottom
CT87  0.22U_0402_16V7K  [C_0402]  33.45 90.45 90 top
CT88  0.1U_0201_10V6K  [C_0201]  31.07 102.64 180 bottom
CT89  1U_0402_10V6K  [C_0402]  31.24 103.4 180 bottom
CT90  1U_0402_10V6K  [C_0402]  36.3 100.29 180 bottom
CT91  2.2U_0402_10V6M  [C_0402]  29.64 100.69 270 bottom
CT92  0.1U_0402_25V6K  [C_0402]  28.75 100.69 270 bottom
CT93  1U_0402_10V6K  [C_0402]  36.61 104.69 270 bottom
CT94  1U_0603_25V6K  [C_0603]  31.61 111.91 180 bottom
CT95  0.22U_0201_6.3V6K  [C_0201]  12.06 110.67 180 bottom
CT96  0.22U_0201_6.3V6K  [C_0201]  12.06 111.3 180 bottom
CT97  0.22U_0201_6.3V6K  [C_0201]  12.07 118.48 180 bottom
CT98  0.22U_0201_6.3V6K  [C_0201]  12.07 117.91 180 bottom
CT99  0.01U_0201_25V6K~D  [C_0201]  9.7 111.25 270 top
CT100  0.01U_0201_25V6K~D  [C_0201]  9.13 111.25 270 top
CT101  0.01U_0201_25V6K~D  [C_0201]  13.76 120.1 0 top
CT102  0.01U_0201_25V6K~D  [C_0201]  13.76 120.68 0 top
CT103  0.22U_0402_10V6K  [C_0402]  28.44 113.69 180 bottom
CT104  0.22U_0402_10V6K  [C_0402]  28.44 112.71 180 bottom
CT105  0.22U_0402_10V6K  [C_0402]  28 111.85 180 bottom
CT106  0.22U_0402_10V6K  [C_0402]  28 110.96 180 bottom
CT107  0.22U_0402_10V6K  [C_0402]  28 110.07 180 bottom
CT108  0.22U_0402_10V6K  [C_0402]  28 109.18 180 bottom
CT109  0.22U_0402_10V6K  [C_0402]  28 108.29 180 bottom
CT110  0.22U_0402_10V6K  [C_0402]  28 107.4 180 bottom
CT111  0.22U_0402_10V6K  [C_0402]  28 116.42 180 bottom
CT112  0.22U_0402_10V6K  [C_0402]  28 117.31 180 bottom
CT113  0.22U_0402_10V6K  [C_0402]  28.32 114.64 180 bottom
CT114  0.22U_0402_10V6K  [C_0402]  28.32 115.53 180 bottom
CT115  0.1U_0402_25V6  [C_0402]  23.86 104.27 90 bottom
CT116  0.1U_0402_25V6  [C_0402]  22.97 104.27 90 bottom
CT117  4.7U_0402_6.3V6M  [C_0402]  19.49 116.67 180 top
CT118  0.1U_0201_10V6K  [C_0201]  19.45 115.91 180 top
CT119  1U_0402_6.3V6K  [C_0402]  18.54 113.69 180 top
CT122  1U_0402_6.3V6K  [C_0402]  19.47 110.9 0 top
CT189  12P_0402_50V8J  [C_0402]  10.68 116.44 0 top
CT190  82P_0402_50V8J  [C_0402]  10.68 117.36 0 top
CT610  0.01UF_0402_25V7K  [C_0402]  23.72 117.63 0 top
CT611  0.1U_0402_25V6  [C_0402]  26.35 114.39 180 top
CT612  0.01UF_0402_25V7K  [C_0402]  26.79 115.34 180 top
CT614  0.1U_0402_25V6  [C_0402]  23.22 108.09 90 top
CT615  0.01UF_0402_25V7K  [C_0402]  24.94 112.37 270 top
CT616  0.01UF_0402_25V7K  [C_0402]  23.16 115.16 270 top
CT617  0.1U_0402_25V6  [C_0402]  19.88 109.68 0 top
CT618  0.1U_0402_25V6  [C_0402]  26.59 112.37 270 top
CT625  4.7U_0402_6.3V6M  [C_0402]  22.64 118.83 0 bottom
CT626  4.7U_0402_6.3V6M  [C_0402]  20.48 115.28 0 top
CT627  4.7U_0402_6.3V6M  [C_0402]  26.79 116.23 180 top
CT628  4.7U_0402_6.3V6M  [C_0402]  24.05 115.28 270 top
CT629  4.7U_0402_6.3V6M  [C_0402]  23.72 118.52 0 top
CT630  0.33U_0201_6.3V6M  [C_0201]  12.79 116.25 180 bottom
CT631  0.33U_0201_6.3V6M  [C_0201]  12.79 116.82 180 bottom
CT632  0.33U_0201_6.3V6M  [C_0201]  12.98 108.42 180 bottom
CT633  0.33U_0201_6.3V6M  [C_0201]  12.98 108.99 180 bottom
CV1  0.1U_0402_25V6  [C_0402]  107.47 102.71 90 bottom
CV2  0.1U_0402_25V6  [C_0402]  106.58 102.71 90 bottom
CV3  0.1U_0402_25V6  [C_0402]  105.69 102.71 90 bottom
CV4  0.1U_0402_25V6  [C_0402]  104.8 102.71 90 bottom
CV5  0.1U_0402_25V6  [C_0402]  102.26 102.83 0 bottom
CV6  0.1U_0402_25V6  [C_0402]  102.26 103.72 0 bottom
CV7  0.1U_0402_25V6  [C_0402]  334.44 71.58 270 top
CV11  100P_0402_50V8J  [C_0402]  115.48 101.31 0 bottom
CV12  0.1U_0201_10V6K  [C_0201]  109.38 103.85 0 bottom
CV13  1000P_0402_50V7K  [C_0402]  127.41 111.98 270 top
CV14  0.01U_0402_50V7K  [C_0402]  126.27 111.98 270 top
CV15  0.1U_0603_50V7K  [C_0603]  122.84 112.23 270 top
CV16  10U_0603_10V6M  [C_0603]  135.28 106.9 90 bottom
CV17  0.01UF_0402_25V7K  [C_0402]  144.68 106.9 0 bottom
CV18  12P_0402_50V8J  [C_0402]  124.49 103.55 270 top
CV19  82P_0402_50V8J  [C_0402]  125.38 103.55 270 top
CV20  12P_0402_50V8J  [C_0402]  109.25 103.09 0 bottom
CV21  82P_0402_50V8J  [C_0402]  109.25 102.2 0 bottom
CV22  12P_0402_50V8J  [C_0402]  118.9 102.96 0 bottom
CV23  82P_0402_50V8J  [C_0402]  118.9 102.07 0 bottom
CV24  12P_0402_50V8J  [C_0402]  115.47 103.6 0 bottom
CV25  82P_0402_50V8J  [C_0402]  115.47 102.71 0 bottom
CV31  0.1U_0402_25V6  [C_0402]  101.29 120.14 90 top
CV32  0.1U_0402_25V6  [C_0402]  102.15 120.12 90 top
CV33  0.1U_0402_25V6  [C_0402]  104.82 120.09 90 top
CV34  0.1U_0402_25V6  [C_0402]  105.71 120.09 90 top
CV35  0.1U_0402_25V6  [C_0402]  111.71 121.26 90 top
CV36  0.1U_0402_25V6  [C_0402]  112.57 121.26 90 top
CV37  0.1U_0402_25V6  [C_0402]  108.38 121.01 270 top
CV38  0.1U_0402_25V6  [C_0402]  109.27 121.01 270 top
CV39  0.1U_0201_10V6K  [C_0201]  123.4 121.44 180 bottom
CV40  0.1U_0201_10V6K  [C_0201]  112.86 125.25 180 bottom
CV41  10U_0603_10V6M  [C_0603]  113.14 124.36 180 bottom
CV61  0.01UF_0402_25V7K  [C_0402]  280.91 32.47 0 top
CV62  0.1U_0201_10V6K  [C_0201]  269.22 35.46 180 top
CV65  0.1U_0201_10V6K  [C_0201]  271.59 29.89 90 top
CV66  0.1U_0201_10V6K  [C_0201]  272.23 29.89 90 top
CV67  0.1U_0201_10V6K  [C_0201]  274.58 30.41 90 top
CV68  0.1U_0201_10V6K  [C_0201]  275.21 30.41 90 top
CV69  0.1U_0201_10V6K  [C_0201]  275.85 30.41 90 top
CV70  0.1U_0201_10V6K  [C_0201]  276.48 30.41 90 top
CV71  0.1U_0201_10V6K  [C_0201]  277.12 30.41 90 top
CV72  0.1U_0201_10V6K  [C_0201]  277.75 30.41 90 top
CV73  0.1U_0201_10V6K  [C_0201]  268.61 36.08 0 top
CV74  0.1U_0201_10V6K  [C_0201]  268.61 36.72 0 top
CV75  2.2U_0402_6.3V6M  [C_0402]  280.91 33.36 0 top
CV100  0.1U_0402_25V6  [C_0402]  332.91 71.35 270 top
CV101  0.1U_0402_25V6  [C_0402]  330.93 69.11 0 top
CV102  4.7U_0402_6.3V6M  [C_0402]  330.93 68.1 0 top
CV103  0.1U_0402_25V6  [C_0402]  322.74 71.34 180 top
CV104  0.1U_0402_25V6  [C_0402]  329.61 74.83 90 top
CV105  2.2U_0402_25V6K  [C_0402]  330.5 74.83 90 top
CV106  0.1U_0402_25V6  [C_0402]  328.34 74.83 90 top
CV107  0.1U_0402_10V7K  [C_0402]  321.85 70.45 0 top
CV108  0.1U_0402_10V7K  [C_0402]  321.85 69.56 0 top
CV109  0.1U_0402_10V7K  [C_0402]  321.85 68.67 0 top
CV110  0.1U_0402_10V7K  [C_0402]  321.85 67.78 0 top
CV111  0.1U_0402_10V7K  [C_0402]  321.85 73.12 0 top
CV112  0.1U_0402_10V7K  [C_0402]  321.85 72.23 0 top
CV126  12P_0402_50V8J  [C_0402]  357.68 104.09 90 top
CV127  12P_0402_50V8J  [C_0402]  357.68 101.68 90 top
CV128  12P_0402_50V8J  [C_0402]  357.81 98.88 90 top
CV129  3.3P_0402_50V8C  [C_0402]  359.84 105 270 top
CV130  3.3P_0402_50V8C  [C_0402]  359.84 102.59 270 top
CV131  3.3P_0402_50V8C  [C_0402]  359.96 99.8 270 top
CV132  2P_0402_50V8C~D  [C_0402]  359.58 88.37 270 bottom
CV133  2P_0402_50V8C~D  [C_0402]  359.58 99.83 270 bottom
CV134  1U_0402_6.3V6K  [C_0402]  359.79 97.94 180 bottom
CV135  .1U_0402_16V7K  [C_0402]  359.46 85.97 180 bottom
CV631  2.2U_0402_6.3V6M  [C_0402]  269.55 32.51 180 top
CV632  0.1U_0402_25V6  [C_0402]  154.13 95.59 270 bottom
CV633  2200P_0402_50V7K  [C_0402]  144.41 96.19 270 bottom
CV634  0.1U_0402_25V6  [C_0402]  141.72 96.14 0 bottom
CV635  2200P_0402_50V7K  [C_0402]  147.2 92.16 270 bottom
CV636  0.1U_0402_25V6  [C_0402]  144.99 94.29 180 bottom
CV1635  0.1U_0402_25V6K  [C_0402]  125.28 100.28 180 top
CV1638  0.1U_0402_25V6K  [C_0402]  131.89 97.37 180 top
CZ1  0.1U_0201_10V6K  [C_0201]  118.86 103.72 0 bottom
CZ2  0.1U_0201_10V6K  [C_0201]  123.62 103.44 270 top
CZ3  100P_0402_50V8J  [C_0402]  135.92 112.51 270 top
CZ4  100P_0402_50V8J  [C_0402]  308.25 63.78 180 top
CZ5  100P_0402_50V8J  [C_0402]  308.23 64.67 180 top
CZ6  100P_0402_50V8J~D  [C_0402]  304.49 37.83 0 bottom
CZ7  100P_0402_50V8J~D  [C_0402]  292.16 14.38 180 top
CZ8  100P_0402_50V8J~D  [C_0402]  292.15 15.25 180 top
CZ9  100P_0402_50V8J~D  [C_0402]  292.15 16.14 180 top
CZ10  0.1U_0402_25V6  [C_0402]  338.27 49.23 90 bottom
CZ11  0.1U_0402_25V6  [C_0402]  339.16 49.23 90 bottom
CZ12  0.1U_0402_25V6  [C_0402]  291.24 31.33 0 bottom
CZ13  0.1U_0402_25V6  [C_0402]  291.24 30.44 0 bottom
CZ17  .047U_0402_16V7K  [C_0402]  342.93 63.21 90 bottom
CZ18  .047U_0402_16V7K  [C_0402]  325.02 63.34 90 bottom
CZ19  33P_0402_50V8J  [C_0402]  324.13 63.34 90 bottom
CZ20  22U_0603_6.3V6M  [C_0603]  342.87 59.8 180 top
CZ21  33P_0402_50V8J  [C_0402]  342.04 63.21 90 bottom
CZ23  47P_0402_50V8J  [C_0402]  343.82 63.21 90 bottom
CZ24  100P_0402_50V8J  [C_0402]  323.24 63.34 90 bottom
CZ25  2200P_0402_50V7K  [C_0402]  322.36 63.34 90 bottom
CZ26  100U_B2_6.3VM_R35M  [C_B2]  347.26 58.06 90 bottom
CZ27  10U_0603_10V6M  [C_0603]  303.45 40.6 180 top
CZ28  0.01UF_0402_25V7K  [C_0402]  304.47 38.71 0 bottom
CZ29  0.01UF_0402_25V7K  [C_0402]  304.47 39.6 0 bottom
CZ30  0.1U_0201_10V6K  [C_0201]  304.47 20.85 90 bottom
CZ31  0.1U_0201_10V6K  [C_0201]  305.1 20.85 90 bottom
CZ32  4.7U_0603_6.3V6K  [C_0603]  296.13 17.02 90 top
CZ33  15P_0402_50V8J  [C_0402]  305.8 19.32 0 bottom
CZ34  15P_0402_50V8J  [C_0402]  304.86 18.26 270 bottom
CZ35  15P_0402_50V8J  [C_0402]  304.47 40.49 0 bottom
CZ36  15P_0402_50V8J  [C_0402]  304.45 41.38 0 bottom
CZ37  4.7U_0402_6.3V6M  [C_0402]  350.42 52.03 180 bottom
CZ38  47P_0402_50V8J  [C_0402]  350.42 48.48 180 bottom
CZ39  33P_0402_50V8J  [C_0402]  350.42 46.19 180 bottom
CZ40  33P_0402_50V8J  [C_0402]  350.42 50.38 180 bottom
CZ41  0.1U_0402_25V6  [C_0402]  350.42 53.05 180 bottom
CZ50  0.1U_0201_10V6K  [C_0201]  245.79 34.78 90 top
CZ51  0.1U_0201_10V6K  [C_0201]  249.08 34.28 90 top
CZ52  10U_0603_10V6M  [C_0603]  249.99 34.19 90 top
CZ53  0.1U_0201_10V6K  [C_0201]  242.53 29.62 180 top
CZ54  0.1U_0201_10V6K  [C_0201]  242.33 27.81 180 top
CZ55  10U_0603_10V6M  [C_0603]  242.54 28.7 180 top
CZ56  0.1U_0402_25V6  [C_0402]  243.63 24.71 90 top
CZ57  12P_0402_50V8J  [C_0402]  254.2 33.25 90 top
CZ58  68P_0402_50V8J  [C_0402]  253.33 33.24 90 top
CZ59  12P_0402_50V8J  [C_0402]  241.7 33 0 top
CZ60  68P_0402_50V8J  [C_0402]  241.68 32.11 0 top
CZ61  .047U_0402_16V7K  [C_0402]  300.26 11.14 270 top
CZ62  100P_0402_50V8J  [C_0402]  309.78 10.3 90 bottom
CZ63  100P_0402_50V8J  [C_0402]  308.13 10.3 90 bottom
CZ64  100P_0201_25V7K~D  [C_0201]  304.19 10.25 0 bottom
CZ66  100P_0201_25V7K~D  [C_0201]  301.78 10.25 180 bottom
CZ67  100P_0201_25V7K~D  [C_0201]  303.31 10.25 180 bottom
CZ68  100P_0201_25V7K~D  [C_0201]  306.35 10.38 0 bottom
CZ69  68P_0402_50V8J  [C_0402]  304.32 11.14 90 bottom
CZ71  68P_0402_50V8J  [C_0402]  301.78 11.14 180 bottom
CZ72  68P_0402_50V8J  [C_0402]  303.31 11.14 90 bottom
CZ73  68P_0402_50V8J  [C_0402]  306.29 11.2 0 bottom
CZ75  10U_0402_6.3V6M  [C_0402]  245.03 34.75 90 top
CZ80  10P_0402_50V8J  [C_0402]  154.35 9.25 270 bottom
CZ81  10P_0402_50V8J  [C_0402]  154.35 6.3 90 bottom
CZ82  0.1U_0201_10V6K  [C_0201]  313.1 20.56 90 bottom
CZ83  68P_0402_50V8J  [C_0402]  140.75 8.6 270 top
CZ84  68P_0402_50V8J  [C_0402]  130.73 9.5 270 bottom
CZ85  68P_0402_50V8J  [C_0402]  135.63 11.33 180 bottom
CZ86  68P_0402_50V8J  [C_0402]  137.41 11.33 180 bottom
CZ87  68P_0402_50V8J  [C_0402]  138.27 11.33 0 bottom
CZ88  68P_0402_50V8J  [C_0402]  149.27 8.33 90 bottom
CZ89  68P_0402_50V8J  [C_0402]  149.27 7.21 270 bottom
CZ90  0.1U_0201_10V6K  [C_0201]  139.98 8.6 270 top
CZ91  0.1U_0201_10V6K  [C_0201]  137.08 8.7 270 top
CZ92  0.1U_0201_10V6K  [C_0201]  136.44 8.7 270 top
CZ93  0.1U_0201_10V6K  [C_0201]  347.43 109.88 180 bottom
CZ100  1U_0402_6.3V6K  [C_0402]  130.55 93.37 180 top
CZ101  0.1U_0402_10V7K  [C_0402]  130.2 87.85 180 top
CZ102  1U_0402_6.3V6K  [C_0402]  71.88 59.84 180 bottom
CZ103  0.1U_0201_10V6K  [C_0201]  73.07 61.24 270 bottom
CZ104  0.1U_0402_10V7K  [C_0402]  153.97 52.98 90 bottom
CZ105  1U_0402_6.3V6K  [C_0402]  144.3 70.7 0 top
CZ106  0.1U_0402_10V7K  [C_0402]  144.68 76.04 0 top
CZ109  470P_0402_50V7K  [C_0402]  311.43 70.19 180 top
CZ110  470P_0402_50V7K  [C_0402]  311.43 71.08 180 top
CZ111  0.1U_0201_10V6K  [C_0201]  311.43 71.85 180 top
CZ112  0.1U_0201_10V6K  [C_0201]  193.83 7.46 90 top
CZ113  470P_0402_50V7K  [C_0402]  194.59 7.58 90 top
CZ114  1000P_0402_50V7K  [C_0402]  195.48 7.58 90 top
